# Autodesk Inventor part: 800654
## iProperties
Created: 2007-10
Part Number: 800654
Document SubType Name: Modeling
Designer: AL
Density: 8.08 g/cm^3
Mass: 7.46672 g
Surface Area: 6.63399 cm^2
Volume: 0.924099 cm^3
Material: Stainless Steel
Description: PIVOT PIN
Component Category: Fasteners
Author: AL
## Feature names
1. Revolution1
